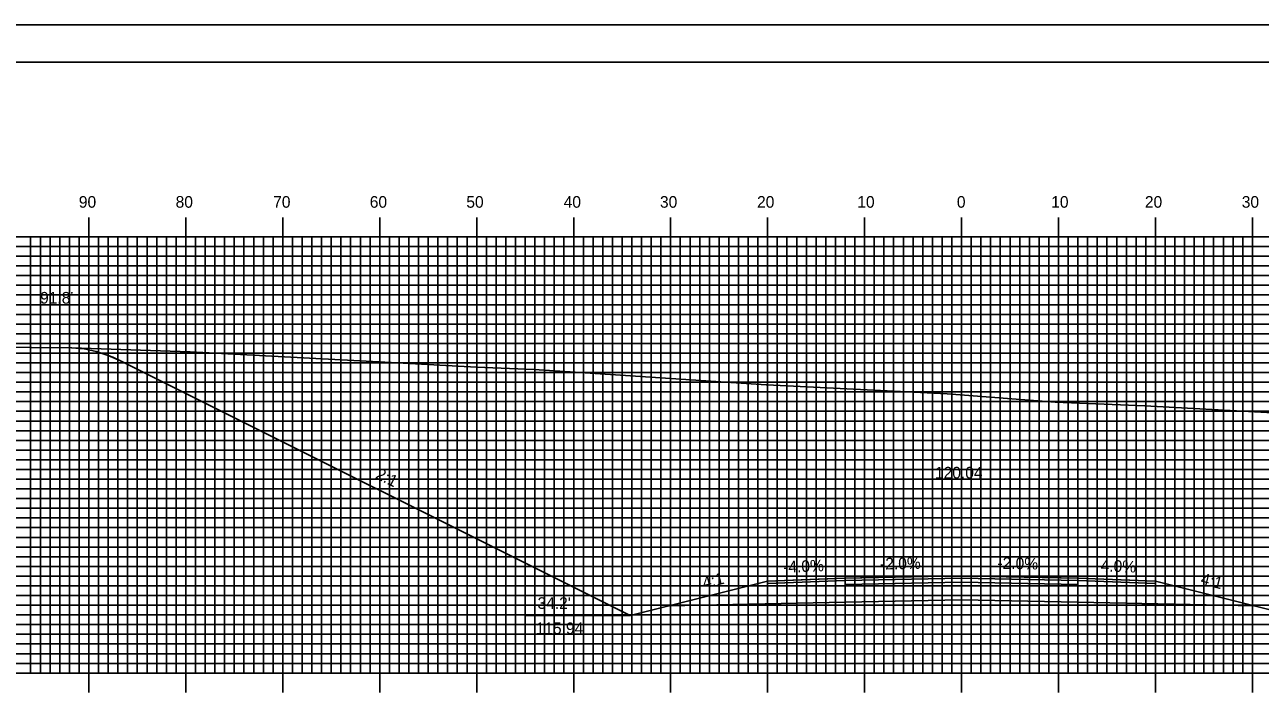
# Model space of a CAD drawing. Extents: x 1770448 to 1770792, y 442591 to 442811.
# Drawn here: x 1770517.4 to 1770644.9, y 442741.2 to 442810.5 of the extents above; entities that cross this region are included whole.
import ezdxf

# ---------------------------------------------------------------- set-up
doc = ezdxf.new("R2010")
doc.units = 0
for name, color, linetype in [('ANNOTATION', 7, 'Continuous'), ('BORDER', 7, 'Continuous'), ('D_Roadway_Centerline', 7, 'Continuous'), ('D_Roadway_Centerline_Text', 7, 'Continuous'), ('D_Roadway_Edge_Shoulder', 7, 'Continuous'), ('D_Roadway_Edge_TW', 7, 'Continuous'), ('D_Roadway_Pavement', 7, 'Continuous'), ('D_Roadway_SlopeLines', 7, 'Continuous'), ('D_Roadway_SubGrade', 7, 'Continuous'), ('D_Text_Standard', 7, 'Continuous'), ('H_V ANNOTATION', 7, 'Continuous'), ('MAJOR', 7, 'Continuous'), ('MINOR', 7, 'Continuous'), ('PDRAIN', 7, 'Continuous'), ('PLOT BOUNDARY', 7, 'Continuous'), ('S_Roadway_Centerline', 7, 'Continuous')]:
    doc.layers.add(name, color=color, linetype=linetype)

msp = doc.modelspace()

# ---------------------------------------------------------------- linework, layer by layer
at = {"layer": 'BORDER'}
msp.add_lwpolyline([(1770464.44, 442596.67), (1770784.44, 442596.67), (1770784.44, 442806.67), (1770464.44, 442806.67)], close=True, dxfattribs=at)
at = {"layer": 'D_Roadway_Centerline'}
msp.add_lwpolyline([(1770522.3, 442777.22), (1770523.55, 442777.1), (1770524.8, 442776.84), (1770526.05, 442776.44), (1770526.51, 442776.24), (1770527.3, 442775.88), (1770579.86, 442749.6), (1770579.87, 442749.6), (1770581.93, 442750.12), (1770583.87, 442750.6), (1770594.04, 442753.15), (1770599.27, 442753.36), (1770602.04, 442753.47), (1770609.89, 442753.62), (1770614.04, 442753.71), (1770618.66, 442753.61), (1770626.04, 442753.47), (1770630.49, 442753.29), (1770634.04, 442753.15), (1770644.21, 442750.6), (1770644.22, 442750.6), (1770648.22, 442749.6)], dxfattribs=at)
at = {"layer": 'D_Roadway_Edge_Shoulder'}
for points in [[(1770602.04, 442753.47), (1770594.04, 442753.15), (1770594.04, 442752.9), (1770602.04, 442753.22)], [(1770626.04, 442753.47), (1770634.04, 442753.15), (1770634.04, 442752.9), (1770626.04, 442753.22)]]:
    msp.add_lwpolyline(points, close=True, dxfattribs=at)
at = {"layer": 'D_Roadway_Edge_TW'}
msp.add_lwpolyline([(1770602.04, 442753.22), (1770602.04, 442753.47), (1770614.04, 442753.71), (1770626.04, 442753.47), (1770626.04, 442753.22), (1770614.04, 442753.46)], close=True, dxfattribs=at)
at = {"layer": 'D_Roadway_Pavement'}
msp.add_lwpolyline([(1770602.04, 442752.8), (1770602.04, 442753.22), (1770614.04, 442753.46), (1770626.04, 442753.22), (1770626.04, 442752.8), (1770614.04, 442753.04)], close=True, dxfattribs=at)
at = {"layer": 'D_Roadway_SlopeLines'}
for points in [[(1770579.87, 442749.6), (1770527.3, 442775.88), (1770526.05, 442776.44), (1770524.8, 442776.84), (1770523.55, 442777.1), (1770522.3, 442777.22)], [(1770594.04, 442753.15), (1770579.87, 442749.6)], [(1770634.04, 442753.15), (1770648.22, 442749.6)]]:
    msp.add_lwpolyline(points, dxfattribs=at)
at = {"layer": 'D_Roadway_SubGrade'}
msp.add_lwpolyline([(1770602.04, 442750.97), (1770583.87, 442750.6), (1770594.04, 442753.15), (1770594.04, 442752.9), (1770602.04, 442753.22), (1770614.04, 442753.46), (1770626.04, 442753.22), (1770634.04, 442752.9), (1770634.04, 442753.15), (1770644.22, 442750.6), (1770626.04, 442750.97), (1770614.04, 442751.21)], close=True, dxfattribs=at)
at = {"layer": 'MAJOR'}
for p, q in [((1770524.04, 442790.67), (1770524.04, 442788.67)), ((1770534.04, 442790.67), (1770534.04, 442788.67)), ((1770544.04, 442790.67), (1770544.04, 442788.67)), ((1770554.04, 442790.67), (1770554.04, 442788.67)), ((1770564.04, 442790.67), (1770564.04, 442788.67)), ((1770574.04, 442790.67), (1770574.04, 442788.67)), ((1770584.04, 442790.67), (1770584.04, 442788.67)), ((1770594.04, 442790.67), (1770594.04, 442788.67)), ((1770604.04, 442790.67), (1770604.04, 442788.67)), ((1770614.04, 442790.67), (1770614.04, 442788.67)), ((1770624.04, 442790.67), (1770624.04, 442788.67)), ((1770634.04, 442790.67), (1770634.04, 442788.67)), ((1770644.04, 442790.67), (1770644.04, 442788.67)), ((1770474.04, 442788.67), (1770754.04, 442788.67)), ((1770474.04, 442788.67), (1770754.04, 442788.67)), ((1770524.04, 442743.67), (1770524.04, 442788.67)), ((1770534.04, 442743.67), (1770534.04, 442788.67)), ((1770544.04, 442743.67), (1770544.04, 442788.67)), ((1770554.04, 442743.67), (1770554.04, 442788.67)), ((1770564.04, 442743.67), (1770564.04, 442788.67)), ((1770574.04, 442743.67), (1770574.04, 442788.67)), ((1770584.04, 442743.67), (1770584.04, 442788.67)), ((1770594.04, 442743.67), (1770594.04, 442788.67)), ((1770604.04, 442743.67), (1770604.04, 442788.67)), ((1770614.04, 442743.67), (1770614.04, 442788.67)), ((1770624.04, 442743.67), (1770624.04, 442788.67)), ((1770634.04, 442743.67), (1770634.04, 442788.67)), ((1770644.04, 442743.67), (1770644.04, 442788.67)), ((1770474.04, 442783.67), (1770754.04, 442783.67)), ((1770474.04, 442778.67), (1770754.04, 442778.67)), ((1770474.04, 442773.67), (1770754.04, 442773.67)), ((1770474.04, 442768.67), (1770754.04, 442768.67)), ((1770474.04, 442763.67), (1770754.04, 442763.67)), ((1770474.04, 442758.67), (1770754.04, 442758.67)), ((1770474.04, 442753.67), (1770754.04, 442753.67)), ((1770474.04, 442748.67), (1770754.04, 442748.67)), ((1770474.04, 442743.67), (1770754.04, 442743.67)), ((1770474.04, 442743.67), (1770754.04, 442743.67)), ((1770524.04, 442741.66), (1770524.04, 442743.67)), ((1770534.04, 442741.66), (1770534.04, 442743.67)), ((1770544.04, 442741.66), (1770544.04, 442743.67)), ((1770554.04, 442741.66), (1770554.04, 442743.67)), ((1770564.04, 442741.66), (1770564.04, 442743.67)), ((1770574.04, 442741.66), (1770574.04, 442743.67)), ((1770584.04, 442741.66), (1770584.04, 442743.67)), ((1770594.04, 442741.66), (1770594.04, 442743.67)), ((1770604.04, 442741.66), (1770604.04, 442743.67)), ((1770614.04, 442741.66), (1770614.04, 442743.67)), ((1770624.04, 442741.66), (1770624.04, 442743.67)), ((1770634.04, 442741.66), (1770634.04, 442743.67)), ((1770644.04, 442741.66), (1770644.04, 442743.67))]:
    msp.add_line(p, q, dxfattribs=at)
at = {"layer": 'MINOR'}
for p, q in [((1770518.04, 442743.67), (1770518.04, 442788.67)), ((1770519.04, 442743.67), (1770519.04, 442788.67)), ((1770520.04, 442743.67), (1770520.04, 442788.67)), ((1770521.04, 442743.67), (1770521.04, 442788.67)), ((1770522.04, 442743.67), (1770522.04, 442788.67)), ((1770523.04, 442743.67), (1770523.04, 442788.67)), ((1770525.04, 442743.67), (1770525.04, 442788.67)), ((1770526.04, 442743.67), (1770526.04, 442788.67)), ((1770527.04, 442743.67), (1770527.04, 442788.67)), ((1770528.04, 442743.67), (1770528.04, 442788.67)), ((1770529.04, 442743.67), (1770529.04, 442788.67)), ((1770530.04, 442743.67), (1770530.04, 442788.67)), ((1770531.04, 442743.67), (1770531.04, 442788.67)), ((1770532.04, 442743.67), (1770532.04, 442788.67)), ((1770533.04, 442743.67), (1770533.04, 442788.67)), ((1770535.04, 442743.67), (1770535.04, 442788.67)), ((1770536.04, 442743.67), (1770536.04, 442788.67)), ((1770537.04, 442743.67), (1770537.04, 442788.67)), ((1770538.04, 442743.67), (1770538.04, 442788.67)), ((1770539.04, 442743.67), (1770539.04, 442788.67)), ((1770540.04, 442743.67), (1770540.04, 442788.67)), ((1770541.04, 442743.67), (1770541.04, 442788.67)), ((1770542.04, 442743.67), (1770542.04, 442788.67)), ((1770543.04, 442743.67), (1770543.04, 442788.67)), ((1770545.04, 442743.67), (1770545.04, 442788.67)), ((1770546.04, 442743.67), (1770546.04, 442788.67)), ((1770547.04, 442743.67), (1770547.04, 442788.67)), ((1770548.04, 442743.67), (1770548.04, 442788.67)), ((1770549.04, 442743.67), (1770549.04, 442788.67)), ((1770550.04, 442743.67), (1770550.04, 442788.67)), ((1770551.04, 442743.67), (1770551.04, 442788.67)), ((1770552.04, 442743.67), (1770552.04, 442788.67)), ((1770553.04, 442743.67), (1770553.04, 442788.67)), ((1770555.04, 442743.67), (1770555.04, 442788.67)), ((1770556.04, 442743.67), (1770556.04, 442788.67)), ((1770557.04, 442743.67), (1770557.04, 442788.67)), ((1770558.04, 442743.67), (1770558.04, 442788.67)), ((1770559.04, 442743.67), (1770559.04, 442788.67)), ((1770560.04, 442743.67), (1770560.04, 442788.67)), ((1770561.04, 442743.67), (1770561.04, 442788.67)), ((1770562.04, 442743.67), (1770562.04, 442788.67)), ((1770563.04, 442743.67), (1770563.04, 442788.67)), ((1770565.04, 442743.67), (1770565.04, 442788.67)), ((1770566.04, 442743.67), (1770566.04, 442788.67)), ((1770567.04, 442743.67), (1770567.04, 442788.67)), ((1770568.04, 442743.67), (1770568.04, 442788.67)), ((1770569.04, 442743.67), (1770569.04, 442788.67)), ((1770570.04, 442743.67), (1770570.04, 442788.67)), ((1770571.04, 442743.67), (1770571.04, 442788.67)), ((1770572.04, 442743.67), (1770572.04, 442788.67)), ((1770573.04, 442743.67), (1770573.04, 442788.67)), ((1770575.04, 442743.67), (1770575.04, 442788.67)), ((1770576.04, 442743.67), (1770576.04, 442788.67)), ((1770577.04, 442743.67), (1770577.04, 442788.67)), ((1770578.04, 442743.67), (1770578.04, 442788.67)), ((1770579.04, 442743.67), (1770579.04, 442788.67)), ((1770580.04, 442743.67), (1770580.04, 442788.67)), ((1770581.04, 442743.67), (1770581.04, 442788.67)), ((1770582.04, 442743.67), (1770582.04, 442788.67)), ((1770583.04, 442743.67), (1770583.04, 442788.67)), ((1770585.04, 442743.67), (1770585.04, 442788.67)), ((1770586.04, 442743.67), (1770586.04, 442788.67)), ((1770587.04, 442743.67), (1770587.04, 442788.67)), ((1770588.04, 442743.67), (1770588.04, 442788.67)), ((1770589.04, 442743.67), (1770589.04, 442788.67)), ((1770590.04, 442743.67), (1770590.04, 442788.67)), ((1770591.04, 442743.67), (1770591.04, 442788.67)), ((1770592.04, 442743.67), (1770592.04, 442788.67)), ((1770593.04, 442743.67), (1770593.04, 442788.67)), ((1770595.04, 442743.67), (1770595.04, 442788.67)), ((1770596.04, 442743.67), (1770596.04, 442788.67)), ((1770597.04, 442743.67), (1770597.04, 442788.67)), ((1770598.04, 442743.67), (1770598.04, 442788.67)), ((1770599.04, 442743.67), (1770599.04, 442788.67)), ((1770600.04, 442743.67), (1770600.04, 442788.67)), ((1770601.04, 442743.67), (1770601.04, 442788.67)), ((1770602.04, 442743.67), (1770602.04, 442788.67)), ((1770603.04, 442743.67), (1770603.04, 442788.67)), ((1770605.04, 442743.67), (1770605.04, 442788.67)), ((1770606.04, 442743.67), (1770606.04, 442788.67)), ((1770607.04, 442743.67), (1770607.04, 442788.67)), ((1770608.04, 442743.67), (1770608.04, 442788.67)), ((1770609.04, 442743.67), (1770609.04, 442788.67)), ((1770610.04, 442743.67), (1770610.04, 442788.67)), ((1770611.04, 442743.67), (1770611.04, 442788.67)), ((1770612.04, 442743.67), (1770612.04, 442788.67)), ((1770613.04, 442743.67), (1770613.04, 442788.67)), ((1770615.04, 442743.67), (1770615.04, 442788.67)), ((1770616.04, 442743.67), (1770616.04, 442788.67)), ((1770617.04, 442743.67), (1770617.04, 442788.67)), ((1770618.04, 442743.67), (1770618.04, 442788.67)), ((1770619.04, 442743.67), (1770619.04, 442788.67)), ((1770620.04, 442743.67), (1770620.04, 442788.67)), ((1770621.04, 442743.67), (1770621.04, 442788.67)), ((1770622.04, 442743.67), (1770622.04, 442788.67)), ((1770623.04, 442743.67), (1770623.04, 442788.67)), ((1770625.04, 442743.67), (1770625.04, 442788.67)), ((1770626.04, 442743.67), (1770626.04, 442788.67)), ((1770627.04, 442743.67), (1770627.04, 442788.67)), ((1770628.04, 442743.67), (1770628.04, 442788.67)), ((1770629.04, 442743.67), (1770629.04, 442788.67)), ((1770630.04, 442743.67), (1770630.04, 442788.67)), ((1770631.04, 442743.67), (1770631.04, 442788.67)), ((1770632.04, 442743.67), (1770632.04, 442788.67)), ((1770633.04, 442743.67), (1770633.04, 442788.67)), ((1770635.04, 442743.67), (1770635.04, 442788.67)), ((1770636.04, 442743.67), (1770636.04, 442788.67)), ((1770637.04, 442743.67), (1770637.04, 442788.67)), ((1770638.04, 442743.67), (1770638.04, 442788.67)), ((1770639.04, 442743.67), (1770639.04, 442788.67)), ((1770640.04, 442743.67), (1770640.04, 442788.67)), ((1770641.04, 442743.67), (1770641.04, 442788.67)), ((1770642.04, 442743.67), (1770642.04, 442788.67)), ((1770643.04, 442743.67), (1770643.04, 442788.67)), ((1770474.04, 442787.67), (1770754.04, 442787.67)), ((1770474.04, 442786.67), (1770754.04, 442786.67)), ((1770474.04, 442785.67), (1770754.04, 442785.67)), ((1770474.04, 442784.67), (1770754.04, 442784.67)), ((1770474.04, 442782.67), (1770754.04, 442782.67)), ((1770474.04, 442781.67), (1770754.04, 442781.67)), ((1770474.04, 442780.67), (1770754.04, 442780.67)), ((1770474.04, 442779.67), (1770754.04, 442779.67)), ((1770474.04, 442777.67), (1770754.04, 442777.67)), ((1770474.04, 442776.67), (1770754.04, 442776.67)), ((1770474.04, 442775.67), (1770754.04, 442775.67)), ((1770474.04, 442774.67), (1770754.04, 442774.67)), ((1770474.04, 442772.67), (1770754.04, 442772.67)), ((1770474.04, 442771.67), (1770754.04, 442771.67)), ((1770474.04, 442770.67), (1770754.04, 442770.67)), ((1770474.04, 442769.67), (1770754.04, 442769.67)), ((1770474.04, 442767.67), (1770754.04, 442767.67)), ((1770474.04, 442766.67), (1770754.04, 442766.67)), ((1770474.04, 442765.67), (1770754.04, 442765.67)), ((1770474.04, 442764.67), (1770754.04, 442764.67)), ((1770474.04, 442762.67), (1770754.04, 442762.67)), ((1770474.04, 442761.67), (1770754.04, 442761.67)), ((1770474.04, 442760.67), (1770754.04, 442760.67)), ((1770474.04, 442759.67), (1770754.04, 442759.67)), ((1770474.04, 442757.67), (1770754.04, 442757.67)), ((1770474.04, 442756.67), (1770754.04, 442756.67)), ((1770474.04, 442755.67), (1770754.04, 442755.67)), ((1770474.04, 442754.67), (1770754.04, 442754.67)), ((1770474.04, 442752.67), (1770754.04, 442752.67)), ((1770474.04, 442751.67), (1770754.04, 442751.67)), ((1770474.04, 442750.67), (1770754.04, 442750.67)), ((1770474.04, 442749.67), (1770754.04, 442749.67)), ((1770474.04, 442747.67), (1770754.04, 442747.67)), ((1770474.04, 442746.67), (1770754.04, 442746.67)), ((1770474.04, 442745.67), (1770754.04, 442745.67)), ((1770474.04, 442744.67), (1770754.04, 442744.67))]:
    msp.add_line(p, q, dxfattribs=at)
at = {"layer": 'PDRAIN'}
msp.add_line((1770569.14, 442749.6), (1770579.87, 442749.6), dxfattribs=at)
at = {"layer": 'PLOT BOUNDARY'}
msp.add_lwpolyline([(1770448.25, 442590.55), (1770788.25, 442590.55), (1770788.25, 442810.55), (1770448.25, 442810.55)], close=True, dxfattribs=at)
at = {"layer": 'S_Roadway_Centerline'}
msp.add_lwpolyline([(1770474.04, 442778.99), (1770474.94, 442778.98), (1770478.16, 442778.92), (1770494.94, 442778.54), (1770504.77, 442777.9), (1770513.96, 442777.28), (1770522.24, 442777.22), (1770533.46, 442776.84), (1770534.49, 442776.79), (1770553.95, 442775.76), (1770564.01, 442775.22), (1770569.95, 442774.98), (1770574.19, 442774.71), (1770593.88, 442773.41), (1770593.89, 442773.41), (1770593.95, 442773.4), (1770612.57, 442772.47), (1770623.7, 442771.6), (1770632.95, 442771.24), (1770647.41, 442770.43)], dxfattribs=at)

# ---------------------------------------------------------------- texts
at = {"layer": 'ANNOTATION'}
for s, rotation, p in [('2:1', 333.4345, (1770553.52, 442763.81)), ('-4.0%', 2.2905, (1770595.67, 442754.01)), ('-2.0%', 1.1457, (1770605.65, 442754.34)), ('-2.0%', 358.8542, (1770617.73, 442754.43)), ('-4.0%', 357.7093, (1770627.83, 442754.2)), ('4:1', 14.039, (1770587.49, 442752.37)), ('4:1', 345.9621, (1770638.63, 442752.86))]:
    msp.add_text(s, height=1.2, rotation=rotation, dxfattribs=at).set_placement(p)
for s, p in [("34.2'", (1770570.31, 442750.29)), ('115.94', (1770570.12, 442747.69))]:
    msp.add_text(s, height=1.2, dxfattribs=at).set_placement(p)
at = {"layer": 'D_Roadway_Centerline'}
for s, p in [('C', (1770614.04, 442753.71)), ('L', (1770614.04, 442753.7))]:
    msp.add_text(s, height=0.0146, dxfattribs=at).set_placement(p)
at = {"layer": 'D_Roadway_Centerline_Text'}
msp.add_text('120.04', height=1.2, dxfattribs=at).set_placement((1770611.3, 442763.74))
at = {"layer": 'D_Text_Standard'}
msp.add_text("91.8'", height=1.2, dxfattribs=at).set_placement((1770519.01, 442781.78))
at = {"layer": 'H_V ANNOTATION'}
for s, p in [('90', (1770523.01, 442791.67)), ('80', (1770532.99, 442791.67)), ('70', (1770543.05, 442791.67)), ('60', (1770553.01, 442791.67)), ('50', (1770562.97, 442791.67)), ('40', (1770573.01, 442791.67)), ('30', (1770582.94, 442791.67)), ('20', (1770592.95, 442791.67)), ('10', (1770603.29, 442791.67)), ('0', (1770613.56, 442791.67)), ('10', (1770623.29, 442791.67)), ('20', (1770632.95, 442791.67)), ('30', (1770642.94, 442791.67))]:
    msp.add_text(s, height=1.2, dxfattribs=at).set_placement(p)

doc.saveas('drawing.dxf')
